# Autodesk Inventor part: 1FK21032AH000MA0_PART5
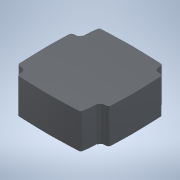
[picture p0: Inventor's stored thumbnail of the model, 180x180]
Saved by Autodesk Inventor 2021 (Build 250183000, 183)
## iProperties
Created: 2025-04
Part Number: 1FK21032AH000MA0_PART5
Material: Generic
Catalog Web Link: www.3dfindit.com
Description: -Servo synchronous motor
Document SubType Name: Modeling
Designer: psAdmin
Mass: 81.3964 g
Surface Area: 120.819 cm^2
Volume: 81.3964 cm^3
Density: 1 g/cm^3
Appearance: PSOLRGB-38-46-56
Category: PARTsolutions
Title: 1FK21032AH000MA0_PART5
Author: Cadenas PARTsolutions
Comments: Servo synchronous motor
Sending System: PARTsolutions
Preprocessor: ST-DEVELOPER v19.3
PSOL_IDENT_0: {$CADENAS_DATA/23d-libs/siemens_ag/_cat_/45/10/1fk21032ah000ma0.prj},213 {VTYP=3D},{NB=1FK21032AH000
PSOL_IDENT_1: MA0_PART5},{LINA=1FK21032AH000MA0_PART5},{NN=1FK21032AH000MA0_PART5},{NOPRJ=TRUE},{DATE=19.08.2025 1
PSOL_IDENT_2: 4:00:35},{GEOMDATE=30.07.2025 02:02:03},{VERSION=},{LINEID=10},{WBVAR=},{WBNUMERIC=}  {NB=1FK21032AH
PSOL_IDENT_3: 000MA0_PART5},{LINA=1FK21032AH000MA0_PART5},{KT=DUMMY},{PREVIEW=../../../_pool_/14/8e/p_d211_xx_0042
PSOL_IDENT_4: 6j.png},{DESCSHORT=SIMOTICS S-1FK2 HD, SINAMICS S210 3AC 400V-480V, 0.59 Nm, 4500 rpm},{DESCLONG=SIM
PSOL_IDENT_5: OTICS S-1FK2 HD servo motor M0=0.64 Nm; PN = 0.28 kW at nN=4500 rpm (380-480 V); PN = 0.167 kW at nN=
PSOL_IDENT_6: 2500 rpm (200-240 V); degree of protection IP64; cylindrical shaft D14 x 30 mm; absolute encoder 22-
PSOL_IDENT_7: bit + 12-bit multiturn (encoder AM22DQC); with OCC interface; plug size M17, rotatable; SIMOTICS S-1
PSOL_IDENT_8: FK2 servomotorfor a wide range of uses in industrial environments. SIMOTICS S‑1FK2 servomotors are c
PSOL_IDENT_9: ompact synchronous motors with a high dynamic performance that set themselves apart as a result of t
PSOL_IDENT_10: heir high power density, degree of protection and overload capability. The motors are available in t
PSOL_IDENT_11: wo variants: as High Dynamic variant (highest dynamic performance as a result of the low intrinsic m
PSOL_IDENT_12: oment of inertia for applications demanding a high dynamic performance with low moved masses) - and
PSOL_IDENT_13: as Compact variant (precise and stable closed-loop control for medium up to large moved masses as a
PSOL_IDENT_14: result of a medium intrinsic moment of inertia). SIMOTICSS‑1FK2 servomotors fully exploit their stre
PSOL_IDENT_15: ngths in a system with the SINAMICSS210 frequency converter and simple connection using the one cabl
PSOL_IDENT_16: e connection (OCC). Advantages include the short control and positioning times, fast and precise cor
PSOL_IDENT_17: rection of disturbing quantities as well as stable control with a high dynamic performance. The serv
PSOL_IDENT_18: o motors can be configured to address a wide range of requirements. For example with and without hol
PSOL_IDENT_19: ding brake, IP64 or IP65 degree of protection, singleturn or multiturn absolute encoders - to name j
PSOL_IDENT_20: ust a few. Further, the servomotors are available in different shaft heights extending from 20 to 10
PSOL_IDENT_21: 0. A shaft sealing ring is available to achieve an IP65 degree of protection and for subsequent moun
PSOL_IDENT_22: ting at the motor or as spare part. SIMOTICS - the optimum motor for each and every motion control a
PSOL_IDENT_23: pplication.},{INTNO=195125335004},{SUPPLIERALTNO=1FK2103-2AH00-0MA0},{MANUID=1FK21032AH000MA0},{MANU
PSOL_IDENT_24: NAME=Siemens},{MANUTYPEDESC=SYNCHRONOUS MOTOR 1FK2 HD 0,64 NM},{AAU732=SIMOTICS},{AAO057=S-1FK2},{AA
PSOL_IDENT_25: U734=SIMOTICS S-1FK2 HD servo motor M0=0.64 Nm; PN = 0.28 kW at nN=4500 rpm (380-480 V); PN = 0.167
PSOL_IDENT_26: kW at nN=2500 rpm (200-240 V); degree of protection IP64; cylindrical shaft D14 x 30 mm; absolute en
PSOL_IDENT_27: coder 22-bit + 12-bit multiturn (encoder AM22DQC); with OCC interface; plug size M17, rotatable;},{A
PSOL_IDENT_28: AW338=SYNCHRONOUS MOTOR 1FK2 HD 0,64 NM},{AAO742=SIMOTICS},{AAO663=4034106444624},{NOCUPEROU=1},{PRI
PSOL_IDENT_29: CEQUANTITY=1},{QUANTITYMIN=1},{QUANTITYINT=1},{CTN=85015100},{COO=RO},{AAO676=1FK2103-2AH00-0MA0},{A
PSOL_IDENT_30: AO677=Siemens AG},{ORDERUNIT=C62},{CONTENTUNIT=C62}
NB: 1FK21032AH000MA0_PART5
NT: Servo synchronous motor
NBSYN: $MANUID._PART5
LINA: 1FK21032AH000MA0_PART5
CATALOG: SIEMENS
PREVIEW: ../../../_pool_/14/8e/p_d211_xx_00426j.png
DESCSHORT: SIMOTICS S-1FK2 HD, SINAMICS S210 3AC 400V-480V, 0.59 Nm, 4500 rpm
DESCLONG: SIMOTICS S-1FK2 HD servo motor M0=0.64 Nm; PN = 0.28 kW at nN=4500 rpm (380-480 V); PN = 0.167 kW at nN=2500 rpm (200-240 V); degree of protection IP64; cylindr
INTNO: 195125335004
SUPPLIERALTNO: 1FK2103-2AH00-0MA0
MANUID: 1FK21032AH000MA0
MANUNAME: Siemens
MANUTYPEDESC: SYNCHRONOUS MOTOR 1FK2 HD 0,64 NM
AAU732: SIMOTICS
AAO057: S-1FK2
AAU734: SIMOTICS S-1FK2 HD servo motor M0=0.64 Nm; PN = 0.28 kW at nN=4500 rpm (380-480 V); PN = 0.167 kW at nN=2500 rpm (200-240 V); degree of protection IP64; cylindr
AAW338: SYNCHRONOUS MOTOR 1FK2 HD 0,64 NM
AAO742: SIMOTICS
AAO663: 4034106444624.0
NOCUPEROU: 1
PRICEQUANTITY: 1
QUANTITYMIN: 1
QUANTITYINT: 1
CTN: 85015100
COO: RO
ARTICLENO: 1FK21032AH000MA0_PART5
BOMINFO: 1FK21032AH000MA0_PART5
CREATOR: CADENAS GmbH
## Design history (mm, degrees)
feature "2025_04_17_15_00_20_0666"
body "Solid1"
